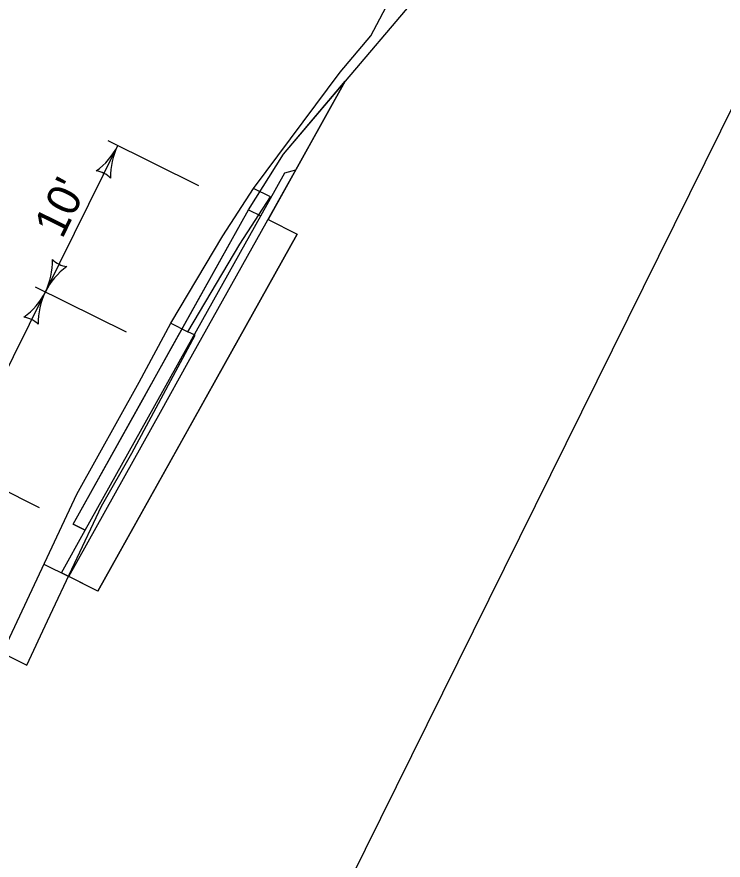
# Model space of a CAD drawing. Extents: x 14104283 to 14128447, y 8633203 to 8671666.
# Drawn here: x 14117876.3 to 14118049.3, y 8668824.8 to 8669031.5 of the extents above; entities that cross this region are included whole.
import ezdxf

# ---------------------------------------------------------------- set-up
doc = ezdxf.new("R2010")
doc.units = 0
for name, color, linetype in [('Default', 7, 'Continuous'), ('dsnCellElements', 7, 'Continuous'), ('dsnShadingPaved', 7, 'Continuous'), ('dsnTextFinalPlan', 7, 'Continuous'), ('TC_Subbase', 7, 'Continuous'), ('TC_SubgradeTreatment', 7, 'Continuous'), ('TC_SubstrataExistingPavement', 7, 'Continuous'), ('Terrain', 7, 'Continuous')]:
    doc.layers.add(name, color=color, linetype=linetype)

# ---------------------------------------------------------------- blocks, each defined once
blk = doc.blocks.new('LT')
at = {"layer": 'dsnCellElements'}
for centre, radius, start, end in [((-3.564, 0), 1.642, 342.2666, 17.7333), ((0, 4.25), 4.25, 241.9275, 270), ((0, -4.25), 4.25, 90, 118.0725)]:
    blk.add_arc(centre, radius, start, end, dxfattribs=at)

msp = doc.modelspace()

# ---------------------------------------------------------------- linework, layer by layer
at = {"layer": 'Default'}
for p, q in [((14117933.08, 8668984.23), (14117936.07, 8668982.75)), ((14117890.1, 8668907.19), (14117893.09, 8668905.71))]:
    msp.add_line(p, q, dxfattribs=at)
for points in [[(14117890.1, 8668907.19), (14117906.75, 8668937.03), (14117913.54, 8668949.21), (14117933.08, 8668984.23)], [(14117893.09, 8668905.71), (14117909.74, 8668935.55), (14117916.53, 8668947.73), (14117936.07, 8668982.75)]]:
    msp.add_lwpolyline(points, dxfattribs=at)
at = {"layer": 'dsnShadingPaved'}
msp.add_lwpolyline([(14117890.1, 8668907.19), (14117933.08, 8668984.23), (14117941.61, 8668997.88), (14117956.75, 8669015.72), (14117937.86, 8668981.86), (14117945.02, 8668978.28), (14117896.19, 8668890.75), (14117887.24, 8668895.21), (14117893.09, 8668905.71)], close=True, dxfattribs=at)
at = {"layer": 'dsnTextFinalPlan'}
for p, q in [((14117898.58, 8669001.17), (14117920.81, 8668990.18)), ((14117883.31, 8668964.1), (14117901.03, 8668999.95)), ((14117862.03, 8668921.07), (14117883.31, 8668964.1)), ((14117880.85, 8668965.31), (14117903.08, 8668954.32)), ((14117859.58, 8668922.28), (14117881.81, 8668911.29))]:
    msp.add_line(p, q, dxfattribs=at)
msp.add_lwpolyline([(14117425.32, 8668197.46), (14117939.89, 8669238.2), (14118120.52, 8669148.89), (14117605.96, 8668108.15)], close=True, dxfattribs=at)
at = {"layer": 'TC_Subbase'}
for p, q in [((14117944.65, 8668994.03), (14117956.75, 8669015.72)), ((14117936.07, 8668982.75), (14117941.93, 8668993.25)), ((14117941.93, 8668993.25), (14117944.65, 8668994.03)), ((14117887.24, 8668895.21), (14117893.09, 8668905.71)), ((14117882.97, 8668897.33), (14117889.03, 8668894.33))]:
    msp.add_line(p, q, dxfattribs=at)
msp.add_lwpolyline([(14117889.03, 8668894.33), (14117911.53, 8668934.66), (14117918.32, 8668946.84), (14117944.65, 8668994.03)], dxfattribs=at)
at = {"layer": 'TC_SubgradeTreatment'}
for p, q in [((14117937.86, 8668981.86), (14117945.02, 8668978.28)), ((14117896.19, 8668890.75), (14117889.03, 8668894.33))]:
    msp.add_line(p, q, dxfattribs=at)
msp.add_lwpolyline([(14117896.19, 8668890.75), (14117918.68, 8668931.08), (14117925.48, 8668943.26), (14117945.02, 8668978.28)], dxfattribs=at)
at = {"layer": 'TC_SubstrataExistingPavement'}
for points in [[(14117914.07, 8668956.41), (14117918.25, 8668954.35), (14117930.94, 8668975.78), (14117938.49, 8668987.41), (14117934.3, 8668989.47)], [(14117872.76, 8668875.6), (14117878.74, 8668872.65), (14117883.84, 8668883.51), (14117897.03, 8668911.61), (14117904.48, 8668924.61), (14117920.04, 8668953.46), (14117918.25, 8668954.35)]]:
    msp.add_lwpolyline(points, dxfattribs=at)
at = {"layer": 'Terrain'}
for points in [[(14117933.08, 8668984.23), (14117941.61, 8668997.88), (14117988.08, 8669052.64), (14118012.27, 8669081.14), (14118030.04, 8669117.09), (14118033.53, 8669142.17), (14118037.15, 8669168.17)], [(14117867.27, 8668864.86), (14117870.35, 8668870.45), (14117873.37, 8668876.88), (14117891.05, 8668914.56), (14117906.28, 8668941.99), (14117914.07, 8668956.41), (14117926.76, 8668977.85), (14117934.3, 8668989.47), (14117955.56, 8669017.99), (14117963.01, 8669026.83), (14118011.55, 8669118.68)]]:
    msp.add_lwpolyline(points, dxfattribs=at)

# ---------------------------------------------------------------- block references
at = {"layer": 'dsnTextFinalPlan'}
for p, xscale, yscale, rotation in [((14117901.03, 8668999.95), 3.942400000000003, 3.9424000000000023, 63.69110745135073), ((14117883.31, 8668964.1), 3.942400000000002, 3.9424000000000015, -116.30889254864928), ((14117883.31, 8668964.1), 3.942400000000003, 3.9424000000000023, 63.69110745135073)]:
    msp.add_blockref('LT', p, dxfattribs=dict(at, xscale=xscale, yscale=yscale, rotation=rotation))

# ---------------------------------------------------------------- texts
msp.add_text("10'", height=8, rotation=63.6911, dxfattribs=at).set_placement((14117887.41, 8668976.88))

doc.saveas('drawing.dxf')
